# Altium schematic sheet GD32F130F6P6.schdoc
size 127 x 101 mm
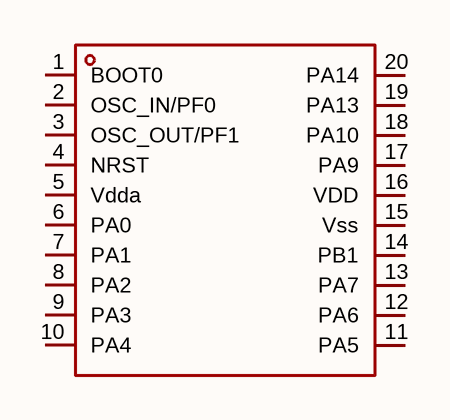
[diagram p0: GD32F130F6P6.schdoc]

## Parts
U?  gd32f130f6p6tr  [TSSOP-20_L6.5-W4.4-P0.65-LS6.4-BL]  (value not drawn)

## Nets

Not connected (* = marked no-connect by the designer): U? 1(BOOT0) 2(OSC_IN/PF0) 3(OSC_OUT/PF1) 4(NRST) 5(Vdda) 6(PA0) 7(PA1) 8(PA2) 9(PA3) 10(PA4) 11(PA5) 12(PA6) 13(PA7) 14(PB1) 15(Vss) 16(VDD) 17(PA9) 18(PA10) 19(PA13) 20(PA14)

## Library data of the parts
U? = gd32f130f6p6tr: CPU内核:ARM Cortex-M3;CPU最大主频:48MHz;CPU位数:-;; Manufacturer: GigaDevice(兆易创新); AddInBom: yes; ModelId: c491f68934b34c649df5890a1d97cd0f; ModelName: TSSOP-20_L6.5-W4.4-H1.0-LS6.4-P0.65; ModelTransform: 251.969,255.906,0,90,0,0,0.0005,0,0; CPU Maximum Speed: 48MHz; Program Storage Size: 32KB; Program Memory Type: FLASH; Number of I/O: 15; ADC (Bit): 12bit; Voltage - Supply: 2.6V~3.6V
